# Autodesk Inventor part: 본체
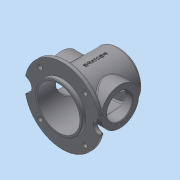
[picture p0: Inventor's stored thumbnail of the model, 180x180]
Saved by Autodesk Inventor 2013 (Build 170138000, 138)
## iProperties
Created: 2018-04
Part Number: 본체
Material: 일반
Document SubType Name: Modeling
Designer: dgall
Density: 1 g/cm^3
Author: dgall
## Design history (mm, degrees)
sketch "스케치1"
  geometry: L1 (0, 64)-(0, -64); L2 (0, 64)-(-50, 64); L3 (-50, 64)-(-50, -64); L4 (0, 56)-(-45, 56); L5 (-45, 56)-(-45, -64); L6 (-50, -64)-(-45, -64); 2 further points
  constraints: 12 end point, 4 perpendicular, 2 horizontal alignment, 1 coincident, 1 midpoint, 1 parallel, 1 point on line, 1 vertical
  dimensions: "d0" = 128 distance of L1.start L1.end; "d2" = 100 diameter of L3 L1; "d3" = 8 distance between parallel lines of L4 L2; "d4" = 90 diameter of L5 L1
revolve "회전1" sketch "스케치1" stored, may be unused: angle "d5" = 90 deg
sketch "스케치2"
  geometry: C1 r 50 at (0, 0) reference; C2 r 40 at (0, 0)
  constraints: 1 centre point, 1 coincident
  dimensions: "d6" = 80 diameter of C2
extrude "돌출1" join sketch "스케치2" distance "d7" = 5; taper "d8" = 0 deg
hole "구멍1" diameter "d11" = 54; stored, may be unused: countersink angle "d15" = 90 deg, drill point angle "d17" = 0 deg; dims "d9" = 10, "d10" = 10, "d12" = 6, "d13" = 4, "d14" = 2, "d16" = 13
node "작업 평면1"
sketch "스케치3"
  geometry: L1 (-64, -50)-(-64, 50) reference; C1 r 40 at (4, 0); 1 further point
  constraints: 1 centre point, 1 horizontal alignment
  dimensions: "d19" = 80 diameter of C1; "d20" = 68 distance from line of L1 C1.centre
extrude "돌출2" join sketch "스케치3" stored distance "d21" = 10; taper "d22" = 0 deg
hole "구멍2" diameter "d25" = 54; stored, may be unused: countersink angle "d29" = 90 deg, drill point angle "d31" = 0 deg; dims "d23" = 10, "d24" = 10, "d26" = 6, "d27" = 4, "d28" = 2, "d30" = 30
sketch "스케치4"
  geometry: C1 r 27 at (0, 0) reference; 2 further points
  constraints: 1 vertical alignment
  dimensions: "d32" = 32.5 distance of C1.centre point (0, 32.5)
hole "구멍3" sketch "스케치4" at (0, 32.5) diameter "d33" = 3.242; stored, may be unused: countersink angle "d37" = 90 deg, drill point angle "d39" = 118 deg; dims "d34" = 8, "d35" = 4, "d36" = 2, "d38" = 10
sketch "스케치5"
  geometry: C1 r 27 at (0, 0) reference; 1 further point
  constraints: 1 vertical alignment
  dimensions: "d43" = 32.5 distance of C1.centre point (0, 32.5)
hole "구멍4" sketch "스케치5" at (0, 32.5) diameter "d44" = 3.242; stored, may be unused: countersink angle "d48" = 90 deg, drill point angle "d50" = 118 deg; dims "d45" = 8, "d46" = 4, "d47" = 2, "d49" = 10
chamfer "모따기1" distance "d54" = 1; stored, may be unused: second distance "d55" = 2, angle "d56" = 45 deg
fillet "모깎기1" dims "d57" = 5
fillet "모깎기2" dims "d58" = 3
node "작업 평면2"
sketch "스케치6"
  geometry: C1 r 50 at (0, 0) reference; C2 r 45 at (0, 0) reference; C3 r 80 at (0, 0); 1 further point
  constraints: 1 centre point, 1 coincident
  dimensions: "d60" = 160 diameter of C3
extrude "돌출3" join sketch "스케치6" distance "d63" = 10; taper "d64" = 0 deg
sketch "스케치7"
  geometry: C1 r 50 at (0, 0) reference; A1 r 80 centre (0, 0) between (-80, 0) and (80, 0) reference; A2 r 15 centre (-80, 0) between (-78.594, -14.934) and (-78.594, 14.934); A3 r 15 centre (80, 0) between (78.594, 14.934) and (78.594, -14.934)
  constraints: 10 point on circle, 2 centre point, 2 horizontal alignment
  dimensions: "d65" = 30 diameter of A2; "d66" = 30 diameter of A3
extrude "돌출4" cut sketch "스케치7" stored distance "d67" = 8; taper "d68" = 0 deg
fillet "모깎기3" dims "d69" = 3
fillet "모깎기4" dims "d70" = 3
sketch "스케치8" dims "d71" = 135
  geometry: L1 (0, 0)-(-80, 0); L2 (0, 0)-(-47.73, 47.73); C1 r 5 at (-47.73, 47.73); A1 r 18 centre (-80, 0) between (-75.031, -17.301) and (-75.031, 17.301) reference; A2 r 77 centre (0, 0) between (-75.031, -17.301) and (75.031, -17.301) reference; 1 further point
  constraints: 4 end point, 2 coincident, 1 centre point, 1 horizontal, 3 other
  dimensions: "d73" = 45 deg angle of L2 L1; "d75" = 10 diameter of C1
extrude "돌출5" cut sketch "스케치8" stored distance "d76" = 8; taper "d77" = 0 deg
chamfer "모따기2" distance "d81" = 1; stored, may be unused: second distance "d82" = 2, angle "d83" = 45 deg
node "작업 평면3"
sketch "스케치9"
  geometry: L1 (49, -64)-(-49, -64) reference; L2 (77.955, -56)-(-77.955, -56) reference; 2 further points
  constraints: 1 vertical alignment, 1 other
  dimensions: "d84" = 70 distance from line of point (0, 14) L2
feature "엠보싱1" sketch "스케치9" dims "d85" = 0.5, "d86" = 0
node "솔리드1"
mirror "대칭1"
pattern_circular "원형 패턴1" dims angle "d41" = 360 deg
mirror "대칭2"
pattern_circular "원형 패턴2" dims angle "d52" = 360 deg
pattern_circular "원형 패턴3" dims angle "d79" = 360 deg
node "절단 모서리 투영1"
other parameters: "d18" = 62, "d59" = -8
